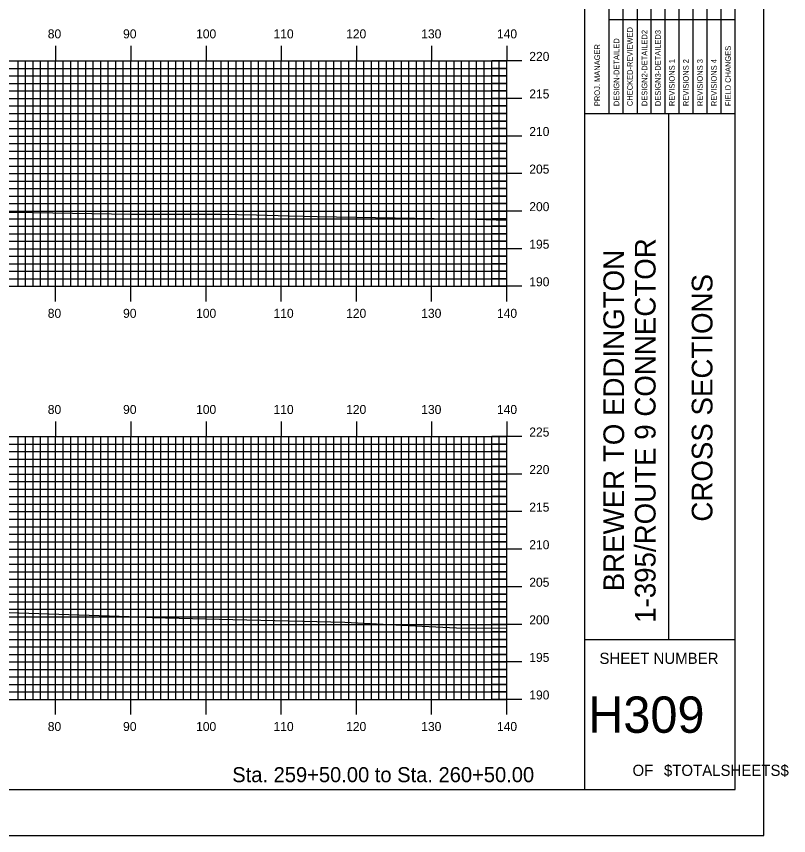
# Model space of a CAD drawing. Extents: x 1805864 to 1806208, y 442591 to 442811.
# Drawn here: x 1806105 to 1806207.7, y 442590.5 to 442699.6 of the extents above; entities that cross this region are included whole.
import ezdxf

# ---------------------------------------------------------------- set-up
doc = ezdxf.new("R2010")
doc.units = 0
for name, color, linetype in [('BORDER', 7, 'Continuous'), ('H_V ANNOTATION', 7, 'Continuous'), ('MAJOR', 7, 'Continuous'), ('MINOR', 7, 'Continuous'), ('PLOT BOUNDARY', 7, 'Continuous'), ('S_Roadway_Centerline', 7, 'Continuous')]:
    doc.layers.add(name, color=color, linetype=linetype)

msp = doc.modelspace()

# ---------------------------------------------------------------- linework, layer by layer
at = {"layer": 'BORDER'}
for p, q in [((1806180.62, 442596.67), (1806180.62, 442806.67)), ((1806180.62, 442686.67), (1806200.62, 442686.67)), ((1806191.8, 442616.67), (1806191.8, 442686.67)), ((1806180.62, 442616.67), (1806200.62, 442616.67))]:
    msp.add_line(p, q, dxfattribs=at)
msp.add_lwpolyline([(1805880.62, 442596.67), (1806200.62, 442596.67), (1806200.62, 442806.67), (1805880.62, 442806.67)], close=True, dxfattribs=at)
for points in [[(1806185.71, 442686.68), (1806185.71, 442721.67)], [(1806187.58, 442721.67), (1806187.58, 442686.68)], [(1806189.44, 442686.68), (1806189.44, 442721.67)], [(1806191.3, 442686.68), (1806191.3, 442721.67)], [(1806193.17, 442686.68), (1806193.17, 442721.67)], [(1806195.03, 442686.68), (1806195.03, 442721.67)], [(1806196.89, 442686.68), (1806196.89, 442721.67)], [(1806198.76, 442686.68), (1806198.76, 442721.67)], [(1806183.85, 442686.68), (1806183.85, 442720.26)], [(1806183.85, 442699.17), (1806200.62, 442699.17)]]:
    msp.add_lwpolyline(points, dxfattribs=at)
at = {"layer": 'MAJOR'}
for p, q in [((1806110.22, 442695.67), (1806110.22, 442693.67)), ((1806120.22, 442695.67), (1806120.22, 442693.67)), ((1806130.22, 442695.67), (1806130.22, 442693.67)), ((1806140.22, 442695.67), (1806140.22, 442693.67)), ((1806150.22, 442695.67), (1806150.22, 442693.67)), ((1806160.22, 442695.67), (1806160.22, 442693.67)), ((1806170.22, 442695.67), (1806170.22, 442693.67)), ((1805890.22, 442693.67), (1806170.22, 442693.67)), ((1805890.22, 442693.67), (1806170.22, 442693.67)), ((1806110.22, 442663.67), (1806110.22, 442693.67)), ((1806120.22, 442663.67), (1806120.22, 442693.67)), ((1806130.22, 442663.67), (1806130.22, 442693.67)), ((1806140.22, 442663.67), (1806140.22, 442693.67)), ((1806150.22, 442663.67), (1806150.22, 442693.67)), ((1806160.22, 442663.67), (1806160.22, 442693.67)), ((1806172.22, 442693.67), (1806168.22, 442693.67)), ((1806170.22, 442663.67), (1806170.22, 442693.67)), ((1806170.22, 442663.67), (1806170.22, 442693.67)), ((1805890.22, 442688.67), (1806170.22, 442688.67)), ((1806172.22, 442688.67), (1806168.22, 442688.67)), ((1805890.22, 442683.67), (1806170.22, 442683.67)), ((1806172.22, 442683.67), (1806168.22, 442683.67)), ((1805890.22, 442678.67), (1806170.22, 442678.67)), ((1806172.22, 442678.67), (1806168.22, 442678.67)), ((1805890.22, 442673.67), (1806170.22, 442673.67)), ((1806172.22, 442673.67), (1806168.22, 442673.67)), ((1805890.22, 442668.67), (1806170.22, 442668.67)), ((1806172.22, 442668.67), (1806168.22, 442668.67)), ((1805890.22, 442663.67), (1806170.22, 442663.67)), ((1805890.22, 442663.67), (1806170.22, 442663.67)), ((1806110.22, 442661.66), (1806110.22, 442663.67)), ((1806120.22, 442661.66), (1806120.22, 442663.67)), ((1806130.22, 442661.66), (1806130.22, 442663.67)), ((1806140.22, 442661.66), (1806140.22, 442663.67)), ((1806150.22, 442661.66), (1806150.22, 442663.67)), ((1806160.22, 442661.66), (1806160.22, 442663.67)), ((1806172.22, 442663.67), (1806168.22, 442663.67)), ((1806170.22, 442661.66), (1806170.22, 442663.67)), ((1806110.22, 442645.67), (1806110.22, 442643.67)), ((1806120.22, 442645.67), (1806120.22, 442643.67)), ((1806130.22, 442645.67), (1806130.22, 442643.67)), ((1806140.22, 442645.67), (1806140.22, 442643.67)), ((1806150.22, 442645.67), (1806150.22, 442643.67)), ((1806160.22, 442645.67), (1806160.22, 442643.67)), ((1806170.22, 442645.67), (1806170.22, 442643.67)), ((1805890.22, 442643.67), (1806170.22, 442643.67)), ((1805890.22, 442643.67), (1806170.22, 442643.67)), ((1806110.22, 442608.67), (1806110.22, 442643.67)), ((1806120.22, 442608.67), (1806120.22, 442643.67)), ((1806130.22, 442608.67), (1806130.22, 442643.67)), ((1806140.22, 442608.67), (1806140.22, 442643.67)), ((1806150.22, 442608.67), (1806150.22, 442643.67)), ((1806160.22, 442608.67), (1806160.22, 442643.67)), ((1806172.22, 442643.67), (1806168.22, 442643.67)), ((1806170.22, 442608.67), (1806170.22, 442643.67)), ((1806170.22, 442608.67), (1806170.22, 442643.67)), ((1805890.22, 442638.67), (1806170.22, 442638.67)), ((1806172.22, 442638.67), (1806168.22, 442638.67)), ((1805890.22, 442633.67), (1806170.22, 442633.67)), ((1806172.22, 442633.67), (1806168.22, 442633.67)), ((1805890.22, 442628.67), (1806170.22, 442628.67)), ((1806172.22, 442628.67), (1806168.22, 442628.67)), ((1805890.22, 442623.67), (1806170.22, 442623.67)), ((1806172.22, 442623.67), (1806168.22, 442623.67)), ((1805890.22, 442618.67), (1806170.22, 442618.67)), ((1806172.22, 442618.67), (1806168.22, 442618.67)), ((1805890.22, 442613.67), (1806170.22, 442613.67)), ((1806172.22, 442613.67), (1806168.22, 442613.67)), ((1805890.22, 442608.67), (1806170.22, 442608.67)), ((1805890.22, 442608.67), (1806170.22, 442608.67)), ((1806110.22, 442606.66), (1806110.22, 442608.67)), ((1806120.22, 442606.66), (1806120.22, 442608.67)), ((1806130.22, 442606.66), (1806130.22, 442608.67)), ((1806140.22, 442606.66), (1806140.22, 442608.67)), ((1806150.22, 442606.66), (1806150.22, 442608.67)), ((1806160.22, 442606.66), (1806160.22, 442608.67)), ((1806172.22, 442608.67), (1806168.22, 442608.67)), ((1806170.22, 442606.66), (1806170.22, 442608.67))]:
    msp.add_line(p, q, dxfattribs=at)
at = {"layer": 'MINOR'}
for p, q in [((1806105.22, 442663.67), (1806105.22, 442693.67)), ((1806106.22, 442663.67), (1806106.22, 442693.67)), ((1806107.22, 442663.67), (1806107.22, 442693.67)), ((1806108.22, 442663.67), (1806108.22, 442693.67)), ((1806109.22, 442663.67), (1806109.22, 442693.67)), ((1806111.22, 442663.67), (1806111.22, 442693.67)), ((1806112.22, 442663.67), (1806112.22, 442693.67)), ((1806113.22, 442663.67), (1806113.22, 442693.67)), ((1806114.22, 442663.67), (1806114.22, 442693.67)), ((1806115.22, 442663.67), (1806115.22, 442693.67)), ((1806116.22, 442663.67), (1806116.22, 442693.67)), ((1806117.22, 442663.67), (1806117.22, 442693.67)), ((1806118.22, 442663.67), (1806118.22, 442693.67)), ((1806119.22, 442663.67), (1806119.22, 442693.67)), ((1806121.22, 442663.67), (1806121.22, 442693.67)), ((1806122.22, 442663.67), (1806122.22, 442693.67)), ((1806123.22, 442663.67), (1806123.22, 442693.67)), ((1806124.22, 442663.67), (1806124.22, 442693.67)), ((1806125.22, 442663.67), (1806125.22, 442693.67)), ((1806126.22, 442663.67), (1806126.22, 442693.67)), ((1806127.22, 442663.67), (1806127.22, 442693.67)), ((1806128.22, 442663.67), (1806128.22, 442693.67)), ((1806129.22, 442663.67), (1806129.22, 442693.67)), ((1806131.22, 442663.67), (1806131.22, 442693.67)), ((1806132.22, 442663.67), (1806132.22, 442693.67)), ((1806133.22, 442663.67), (1806133.22, 442693.67)), ((1806134.22, 442663.67), (1806134.22, 442693.67)), ((1806135.22, 442663.67), (1806135.22, 442693.67)), ((1806136.22, 442663.67), (1806136.22, 442693.67)), ((1806137.22, 442663.67), (1806137.22, 442693.67)), ((1806138.22, 442663.67), (1806138.22, 442693.67)), ((1806139.22, 442663.67), (1806139.22, 442693.67)), ((1806141.22, 442663.67), (1806141.22, 442693.67)), ((1806142.22, 442663.67), (1806142.22, 442693.67)), ((1806143.22, 442663.67), (1806143.22, 442693.67)), ((1806144.22, 442663.67), (1806144.22, 442693.67)), ((1806145.22, 442663.67), (1806145.22, 442693.67)), ((1806146.22, 442663.67), (1806146.22, 442693.67)), ((1806147.22, 442663.67), (1806147.22, 442693.67)), ((1806148.22, 442663.67), (1806148.22, 442693.67)), ((1806149.22, 442663.67), (1806149.22, 442693.67)), ((1806151.22, 442663.67), (1806151.22, 442693.67)), ((1806152.22, 442663.67), (1806152.22, 442693.67)), ((1806153.22, 442663.67), (1806153.22, 442693.67)), ((1806154.22, 442663.67), (1806154.22, 442693.67)), ((1806155.22, 442663.67), (1806155.22, 442693.67)), ((1806156.22, 442663.67), (1806156.22, 442693.67)), ((1806157.22, 442663.67), (1806157.22, 442693.67)), ((1806158.22, 442663.67), (1806158.22, 442693.67)), ((1806159.22, 442663.67), (1806159.22, 442693.67)), ((1806161.22, 442663.67), (1806161.22, 442693.67)), ((1806162.22, 442663.67), (1806162.22, 442693.67)), ((1806163.22, 442663.67), (1806163.22, 442693.67)), ((1806164.22, 442663.67), (1806164.22, 442693.67)), ((1806165.22, 442663.67), (1806165.22, 442693.67)), ((1806166.22, 442663.67), (1806166.22, 442693.67)), ((1806167.22, 442663.67), (1806167.22, 442693.67)), ((1806168.22, 442663.67), (1806168.22, 442693.67)), ((1806169.22, 442663.67), (1806169.22, 442693.67)), ((1805890.22, 442692.67), (1806170.22, 442692.67)), ((1805890.22, 442691.67), (1806170.22, 442691.67)), ((1806170.22, 442692.67), (1806168.22, 442692.67)), ((1806170.22, 442691.67), (1806168.22, 442691.67)), ((1805890.22, 442690.67), (1806170.22, 442690.67)), ((1806170.22, 442690.67), (1806168.22, 442690.67)), ((1805890.22, 442689.67), (1806170.22, 442689.67)), ((1806170.22, 442689.67), (1806168.22, 442689.67)), ((1805890.22, 442687.67), (1806170.22, 442687.67)), ((1806170.22, 442687.67), (1806168.22, 442687.67)), ((1805890.22, 442686.67), (1806170.22, 442686.67)), ((1806170.22, 442686.67), (1806168.22, 442686.67)), ((1805890.22, 442685.67), (1806170.22, 442685.67)), ((1806170.22, 442685.67), (1806168.22, 442685.67)), ((1805890.22, 442684.67), (1806170.22, 442684.67)), ((1806170.22, 442684.67), (1806168.22, 442684.67)), ((1805890.22, 442682.67), (1806170.22, 442682.67)), ((1806170.22, 442682.67), (1806168.22, 442682.67)), ((1805890.22, 442681.67), (1806170.22, 442681.67)), ((1806170.22, 442681.67), (1806168.22, 442681.67)), ((1805890.22, 442680.67), (1806170.22, 442680.67)), ((1805890.22, 442679.67), (1806170.22, 442679.67)), ((1806170.22, 442680.67), (1806168.22, 442680.67)), ((1806170.22, 442679.67), (1806168.22, 442679.67)), ((1805890.22, 442677.67), (1806170.22, 442677.67)), ((1806170.22, 442677.67), (1806168.22, 442677.67)), ((1805890.22, 442676.67), (1806170.22, 442676.67)), ((1806170.22, 442676.67), (1806168.22, 442676.67)), ((1805890.22, 442675.67), (1806170.22, 442675.67)), ((1806170.22, 442675.67), (1806168.22, 442675.67)), ((1805890.22, 442674.67), (1806170.22, 442674.67)), ((1806170.22, 442674.67), (1806168.22, 442674.67)), ((1805890.22, 442672.67), (1806170.22, 442672.67)), ((1806170.22, 442672.67), (1806168.22, 442672.67)), ((1805890.22, 442671.67), (1806170.22, 442671.67)), ((1806170.22, 442671.67), (1806168.22, 442671.67)), ((1805890.22, 442670.67), (1806170.22, 442670.67)), ((1806170.22, 442670.67), (1806168.22, 442670.67)), ((1805890.22, 442669.67), (1806170.22, 442669.67)), ((1806170.22, 442669.67), (1806168.22, 442669.67)), ((1805890.22, 442667.67), (1806170.22, 442667.67)), ((1806170.22, 442667.67), (1806168.22, 442667.67)), ((1805890.22, 442666.67), (1806170.22, 442666.67)), ((1806170.22, 442666.67), (1806168.22, 442666.67)), ((1805890.22, 442665.67), (1806170.22, 442665.67)), ((1806170.22, 442665.67), (1806168.22, 442665.67)), ((1805890.22, 442664.67), (1806170.22, 442664.67)), ((1806170.22, 442664.67), (1806168.22, 442664.67)), ((1806105.22, 442608.67), (1806105.22, 442643.67)), ((1806106.22, 442608.67), (1806106.22, 442643.67)), ((1806107.22, 442608.67), (1806107.22, 442643.67)), ((1806108.22, 442608.67), (1806108.22, 442643.67)), ((1806109.22, 442608.67), (1806109.22, 442643.67)), ((1806111.22, 442608.67), (1806111.22, 442643.67)), ((1806112.22, 442608.67), (1806112.22, 442643.67)), ((1806113.22, 442608.67), (1806113.22, 442643.67)), ((1806114.22, 442608.67), (1806114.22, 442643.67)), ((1806115.22, 442608.67), (1806115.22, 442643.67)), ((1806116.22, 442608.67), (1806116.22, 442643.67)), ((1806117.22, 442608.67), (1806117.22, 442643.67)), ((1806118.22, 442608.67), (1806118.22, 442643.67)), ((1806119.22, 442608.67), (1806119.22, 442643.67)), ((1806121.22, 442608.67), (1806121.22, 442643.67)), ((1806122.22, 442608.67), (1806122.22, 442643.67)), ((1806123.22, 442608.67), (1806123.22, 442643.67)), ((1806124.22, 442608.67), (1806124.22, 442643.67)), ((1806125.22, 442608.67), (1806125.22, 442643.67)), ((1806126.22, 442608.67), (1806126.22, 442643.67)), ((1806127.22, 442608.67), (1806127.22, 442643.67)), ((1806128.22, 442608.67), (1806128.22, 442643.67)), ((1806129.22, 442608.67), (1806129.22, 442643.67)), ((1806131.22, 442608.67), (1806131.22, 442643.67)), ((1806132.22, 442608.67), (1806132.22, 442643.67)), ((1806133.22, 442608.67), (1806133.22, 442643.67)), ((1806134.22, 442608.67), (1806134.22, 442643.67)), ((1806135.22, 442608.67), (1806135.22, 442643.67)), ((1806136.22, 442608.67), (1806136.22, 442643.67)), ((1806137.22, 442608.67), (1806137.22, 442643.67)), ((1806138.22, 442608.67), (1806138.22, 442643.67)), ((1806139.22, 442608.67), (1806139.22, 442643.67)), ((1806141.22, 442608.67), (1806141.22, 442643.67)), ((1806142.22, 442608.67), (1806142.22, 442643.67)), ((1806143.22, 442608.67), (1806143.22, 442643.67)), ((1806144.22, 442608.67), (1806144.22, 442643.67)), ((1806145.22, 442608.67), (1806145.22, 442643.67)), ((1806146.22, 442608.67), (1806146.22, 442643.67)), ((1806147.22, 442608.67), (1806147.22, 442643.67)), ((1806148.22, 442608.67), (1806148.22, 442643.67)), ((1806149.22, 442608.67), (1806149.22, 442643.67)), ((1806151.22, 442608.67), (1806151.22, 442643.67)), ((1806152.22, 442608.67), (1806152.22, 442643.67)), ((1806153.22, 442608.67), (1806153.22, 442643.67)), ((1806154.22, 442608.67), (1806154.22, 442643.67)), ((1806155.22, 442608.67), (1806155.22, 442643.67)), ((1806156.22, 442608.67), (1806156.22, 442643.67)), ((1806157.22, 442608.67), (1806157.22, 442643.67)), ((1806158.22, 442608.67), (1806158.22, 442643.67)), ((1806159.22, 442608.67), (1806159.22, 442643.67)), ((1806161.22, 442608.67), (1806161.22, 442643.67)), ((1806162.22, 442608.67), (1806162.22, 442643.67)), ((1806163.22, 442608.67), (1806163.22, 442643.67)), ((1806164.22, 442608.67), (1806164.22, 442643.67)), ((1806165.22, 442608.67), (1806165.22, 442643.67)), ((1806166.22, 442608.67), (1806166.22, 442643.67)), ((1806167.22, 442608.67), (1806167.22, 442643.67)), ((1806168.22, 442608.67), (1806168.22, 442643.67)), ((1806169.22, 442608.67), (1806169.22, 442643.67)), ((1805890.22, 442642.67), (1806170.22, 442642.67)), ((1806170.22, 442642.67), (1806168.22, 442642.67)), ((1805890.22, 442641.67), (1806170.22, 442641.67)), ((1806170.22, 442641.67), (1806168.22, 442641.67)), ((1805890.22, 442640.67), (1806170.22, 442640.67)), ((1806170.22, 442640.67), (1806168.22, 442640.67)), ((1805890.22, 442639.67), (1806170.22, 442639.67)), ((1806170.22, 442639.67), (1806168.22, 442639.67)), ((1805890.22, 442637.67), (1806170.22, 442637.67)), ((1806170.22, 442637.67), (1806168.22, 442637.67)), ((1805890.22, 442636.67), (1806170.22, 442636.67)), ((1806170.22, 442636.67), (1806168.22, 442636.67)), ((1805890.22, 442635.67), (1806170.22, 442635.67)), ((1806170.22, 442635.67), (1806168.22, 442635.67)), ((1805890.22, 442634.67), (1806170.22, 442634.67)), ((1806170.22, 442634.67), (1806168.22, 442634.67)), ((1805890.22, 442632.67), (1806170.22, 442632.67)), ((1806170.22, 442632.67), (1806168.22, 442632.67)), ((1805890.22, 442631.67), (1806170.22, 442631.67)), ((1805890.22, 442630.67), (1806170.22, 442630.67)), ((1806170.22, 442631.67), (1806168.22, 442631.67)), ((1806170.22, 442630.67), (1806168.22, 442630.67)), ((1805890.22, 442629.67), (1806170.22, 442629.67)), ((1806170.22, 442629.67), (1806168.22, 442629.67)), ((1805890.22, 442627.67), (1806170.22, 442627.67)), ((1806170.22, 442627.67), (1806168.22, 442627.67)), ((1805890.22, 442626.67), (1806170.22, 442626.67)), ((1806170.22, 442626.67), (1806168.22, 442626.67)), ((1805890.22, 442625.67), (1806170.22, 442625.67)), ((1806170.22, 442625.67), (1806168.22, 442625.67)), ((1805890.22, 442624.67), (1806170.22, 442624.67)), ((1806170.22, 442624.67), (1806168.22, 442624.67)), ((1805890.22, 442622.67), (1806170.22, 442622.67)), ((1806170.22, 442622.67), (1806168.22, 442622.67)), ((1805890.22, 442621.67), (1806170.22, 442621.67)), ((1806170.22, 442621.67), (1806168.22, 442621.67)), ((1805890.22, 442620.67), (1806170.22, 442620.67)), ((1806170.22, 442620.67), (1806168.22, 442620.67)), ((1805890.22, 442619.67), (1806170.22, 442619.67)), ((1806170.22, 442619.67), (1806168.22, 442619.67)), ((1805890.22, 442617.67), (1806170.22, 442617.67)), ((1806170.22, 442617.67), (1806168.22, 442617.67)), ((1805890.22, 442616.67), (1806170.22, 442616.67)), ((1806170.22, 442616.67), (1806168.22, 442616.67)), ((1805890.22, 442615.67), (1806170.22, 442615.67)), ((1806170.22, 442615.67), (1806168.22, 442615.67)), ((1805890.22, 442614.67), (1806170.22, 442614.67)), ((1806170.22, 442614.67), (1806168.22, 442614.67)), ((1805890.22, 442612.67), (1806170.22, 442612.67)), ((1806170.22, 442612.67), (1806168.22, 442612.67)), ((1805890.22, 442611.67), (1806170.22, 442611.67)), ((1806170.22, 442611.67), (1806168.22, 442611.67)), ((1805890.22, 442610.67), (1806170.22, 442610.67)), ((1806170.22, 442610.67), (1806168.22, 442610.67)), ((1805890.22, 442609.67), (1806170.22, 442609.67)), ((1806170.22, 442609.67), (1806168.22, 442609.67))]:
    msp.add_line(p, q, dxfattribs=at)
at = {"layer": 'PLOT BOUNDARY'}
msp.add_lwpolyline([(1805864.43, 442590.55), (1806204.43, 442590.55), (1806204.43, 442810.55), (1805864.43, 442810.55)], close=True, dxfattribs=at)
at = {"layer": 'S_Roadway_Centerline'}
for points in [[(1805978.48, 442679.38), (1805999.99, 442677.25), (1806004.2, 442677.05), (1806016.96, 442676.28), (1806022.76, 442676.11), (1806029.55, 442676.04), (1806045.73, 442675.68), (1806055.84, 442675.85), (1806058.78, 442675.76), (1806069.77, 442675.59), (1806079.73, 442675.22), (1806081.03, 442675.24), (1806082.49, 442675.09), (1806100.88, 442673.59), (1806103.55, 442673.53), (1806107.22, 442673.47), (1806120.27, 442673.26), (1806132.04, 442673.29), (1806136.93, 442673.2), (1806141.24, 442673.03), (1806145.01, 442672.98), (1806163.14, 442672.64), (1806166.03, 442672.6), (1806170.22, 442672.45)], [(1806098.9, 442620.42), (1806105.34, 442620.19), (1806121.31, 442619.65), (1806123.07, 442619.58), (1806133.78, 442619.33), (1806148.69, 442618.98), (1806157.17, 442618.52), (1806163.53, 442618.2), (1806170.22, 442618.15)]]:
    msp.add_lwpolyline(points, dxfattribs=at)

# ---------------------------------------------------------------- texts
at = {"layer": 'BORDER'}
for s, height, p in [('CHECKED-REVIEWED', 0.7455, (1806186.98, 442687.65)), ('DESIGN2-DETAILED2', 0.7455, (1806188.92, 442687.65)), ('DESIGN3-DETAILED3', 0.7455, (1806190.71, 442687.65)), ('DESIGN-DETAILED', 0.7455, (1806185.19, 442687.65)), ('PROJ. MANAGER', 0.7455, (1806182.63, 442687.65)), ('FIELD CHANGES', 0.7455, (1806200.03, 442687.65)), ('REVISIONS 1', 0.7455, (1806192.57, 442687.65)), ('REVISIONS 2', 0.7455, (1806194.43, 442687.65)), ('REVISIONS 3', 0.7455, (1806196.3, 442687.65)), ('REVISIONS 4', 0.7455, (1806198.16, 442687.65)), ('1-395/ROUTE 9 CONNECTOR', 2.7557, (1806190.02, 442618.87)), ('BREWER TO EDDINGTON', 2.7557, (1806185.84, 442623.07)), ('CROSS SECTIONS', 2.7557, (1806197.59, 442632.34))]:
    msp.add_text(s, height=height, rotation=90, dxfattribs=at).set_placement(p)
for s, height, p in [('SHEET NUMBER', 1.4905, (1806182.55, 442613.4)), ('H309', 4.839, (1806181.06, 442604.23)), ('$TOTALSHEETS$', 1.4905, (1806191.13, 442598.49)), ('OF', 1.491, (1806186.95, 442598.49))]:
    msp.add_text(s, height=height, dxfattribs=at).set_placement(p)
at = {"layer": 'H_V ANNOTATION'}
for s, height, p in [('80', 1.2, (1806109.17, 442696.67)), ('90', 1.2, (1806119.19, 442696.67)), ('100', 1.2, (1806128.9, 442696.67)), ('110', 1.2, (1806139.2, 442696.67)), ('120', 1.2, (1806148.86, 442696.67)), ('130', 1.2, (1806158.85, 442696.67)), ('140', 1.2, (1806168.92, 442696.67)), ('220', 1.2, (1806173.22, 442693.67)), ('215', 1.2, (1806173.22, 442688.67)), ('210', 1.2, (1806173.22, 442683.67)), ('205', 1.2, (1806173.22, 442678.67)), ('200', 1.2, (1806173.22, 442673.67)), ('195', 1.2, (1806173.22, 442668.67)), ('190', 1.2, (1806173.22, 442663.67)), ('80', 1.2, (1806109.17, 442659.47)), ('90', 1.2, (1806119.19, 442659.47)), ('100', 1.2, (1806128.9, 442659.47)), ('110', 1.2, (1806139.2, 442659.47)), ('120', 1.2, (1806148.86, 442659.47)), ('130', 1.2, (1806158.85, 442659.47)), ('140', 1.2, (1806168.92, 442659.47)), ('80', 1.2, (1806109.17, 442646.67)), ('90', 1.2, (1806119.19, 442646.67)), ('100', 1.2, (1806128.9, 442646.67)), ('110', 1.2, (1806139.2, 442646.67)), ('120', 1.2, (1806148.86, 442646.67)), ('130', 1.2, (1806158.85, 442646.67)), ('140', 1.2, (1806168.92, 442646.67)), ('225', 1.2, (1806173.22, 442643.67)), ('220', 1.2, (1806173.22, 442638.67)), ('215', 1.2, (1806173.22, 442633.67)), ('210', 1.2, (1806173.22, 442628.67)), ('205', 1.2, (1806173.22, 442623.67)), ('200', 1.2, (1806173.22, 442618.67)), ('195', 1.2, (1806173.22, 442613.67)), ('190', 1.2, (1806173.22, 442608.67)), ('80', 1.2, (1806109.17, 442604.47)), ('90', 1.2, (1806119.19, 442604.47)), ('100', 1.2, (1806128.9, 442604.47)), ('110', 1.2, (1806139.2, 442604.47)), ('120', 1.2, (1806148.86, 442604.47)), ('130', 1.2, (1806158.85, 442604.47)), ('140', 1.2, (1806168.92, 442604.47)), ('Sta. 259+50.00 to Sta. 260+50.00', 2.0004, (1806133.71, 442597.66))]:
    msp.add_text(s, height=height, dxfattribs=at).set_placement(p)

doc.saveas('drawing.dxf')
